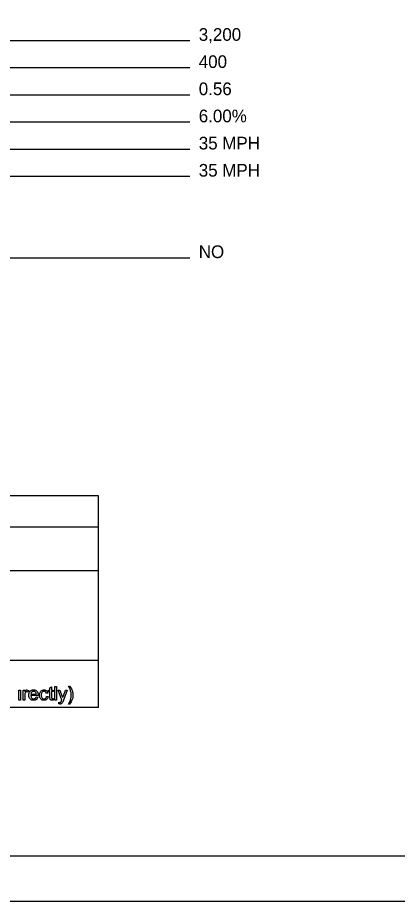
# Model space of a CAD drawing. Extents: x -4 to 116, y -17 to 29.
# Drawn here: x 54.22 to 58.41, y -14.61 to -4.84 of the extents above; entities that cross this region are included whole.
import ezdxf

# ---------------------------------------------------------------- set-up
doc = ezdxf.new("R2010")
doc.units = 0
for name, color, linetype in [('SH_Border', 7, 'Continuous'), ('SH_Cut_Line', 7, 'Continuous'), ('SH_Data', 7, 'Continuous'), ('SH_Text', 7, 'Continuous')]:
    doc.layers.add(name, color=color, linetype=linetype)

msp = doc.modelspace()

# ---------------------------------------------------------------- linework, layer by layer
at = {"layer": 'SH_Border'}
msp.add_lwpolyline([(49.9833, 6.8947), (81.9833, 6.8947), (81.9833, -14.1053), (49.9833, -14.1053)], close=True, dxfattribs=at)
at = {"layer": 'SH_Cut_Line'}
msp.add_lwpolyline([(48.4833, -14.6053), (82.4833, -14.6053), (82.4833, 7.3947), (48.4833, 7.3947)], close=True, dxfattribs=at)
at = {"layer": 'SH_Data'}
for p, q in [((56.1201, -5.0991), (52.6718, -5.0991)), ((56.1201, -5.3991), (53.3556, -5.3991)), ((56.1201, -5.6991), (53.087, -5.6991)), ((56.1201, -5.9991), (52.6718, -5.9991)), ((56.1201, -6.2991), (51.8292, -6.2991)), ((56.1201, -6.5991), (51.7255, -6.5991)), ((56.1201, -7.4991), (51.7502, -7.4991)), ((55.1108, -10.125), (50.8608, -10.125)), ((55.1108, -12.4625), (55.1108, -10.125)), ((50.8608, -10.4666), (55.1108, -10.4666)), ((50.8608, -10.95), (55.1108, -10.95)), ((55.1108, -11.9447), (50.8608, -11.9447)), ((55.1108, -12.4625), (50.8608, -12.4625))]:
    msp.add_line(p, q, dxfattribs=at)
at = {"layer": 'SH_Text'}
for points in [[(54.2342, -12.3814), (54.2342, -12.2726), (54.2526, -12.2726), (54.2526, -12.3814), (54.2342, -12.3814)], [(54.2804, -12.3814), (54.2804, -12.2726), (54.297, -12.2726), (54.297, -12.289)], [(54.3395, -12.276), (54.333, -12.2931)], [(54.5753, -12.3495), (54.5753, -12.2869), (54.5617, -12.2869), (54.5617, -12.2726), (54.5753, -12.2726), (54.5753, -12.2456), (54.5938, -12.2346), (54.5938, -12.2726), (54.6122, -12.2726), (54.6122, -12.2869), (54.5938, -12.2869), (54.5938, -12.3506)], [(54.6298, -12.3814), (54.6298, -12.2312), (54.6482, -12.2312), (54.6482, -12.3814), (54.6298, -12.3814)], [(54.7076, -12.3815), (54.6663, -12.2726), (54.6862, -12.2726), (54.7088, -12.3354)], [(54.7243, -12.336), (54.7476, -12.2726), (54.766, -12.2726), (54.7247, -12.3833)], [(54.7806, -12.2287), (54.7938, -12.2287)], [(54.2988, -12.3244), (54.2988, -12.3814), (54.2804, -12.3814)], [(54.4444, -12.3317), (54.3633, -12.3317)], [(54.3643, -12.3166), (54.4251, -12.3166)], [(54.4249, -12.3463), (54.4439, -12.3487)], [(54.5545, -12.3046), (54.5365, -12.3073)], [(54.5381, -12.3416), (54.5562, -12.344)], [(54.6122, -12.365), (54.6148, -12.3812)], [(54.676, -12.4232), (54.674, -12.4058)], [(54.7938, -12.4256), (54.7806, -12.4256)]]:
    msp.add_lwpolyline(points, dxfattribs=at)
for points in [[(54.297, -12.289), (54.3033, -12.2775), (54.3087, -12.2738), (54.3141, -12.2702), (54.3205, -12.2702), (54.3298, -12.2702), (54.3395, -12.276)], [(54.333, -12.2931), (54.3263, -12.2892), (54.3196, -12.2892), (54.3135, -12.2892), (54.3087, -12.2928), (54.304, -12.2964), (54.3019, -12.3029), (54.2988, -12.3127), (54.2988, -12.3244)], [(54.4439, -12.3487), (54.4394, -12.3654), (54.4272, -12.3746), (54.415, -12.3838), (54.3961, -12.3838), (54.3722, -12.3838), (54.3582, -12.3691), (54.3443, -12.3544), (54.3443, -12.3279), (54.3443, -12.3005), (54.3584, -12.2853), (54.3725, -12.2702), (54.3951, -12.2702), (54.4169, -12.2702), (54.4307, -12.285), (54.4445, -12.2999), (54.4445, -12.3268), (54.4445, -12.3284), (54.4444, -12.3317)], [(54.4251, -12.3166), (54.4238, -12.3028), (54.4181, -12.296), (54.4093, -12.2853), (54.3952, -12.2853), (54.3825, -12.2853), (54.3739, -12.2938), (54.3652, -12.3023), (54.3643, -12.3166)], [(54.5562, -12.344), (54.5532, -12.3627), (54.541, -12.3732), (54.5288, -12.3838), (54.5109, -12.3838), (54.4886, -12.3838), (54.475, -12.3692), (54.4615, -12.3546), (54.4615, -12.3274), (54.4615, -12.3098), (54.4673, -12.2966), (54.4731, -12.2834), (54.4851, -12.2768), (54.497, -12.2702), (54.5111, -12.2702), (54.5288, -12.2702), (54.5401, -12.2791), (54.5513, -12.2881), (54.5545, -12.3046)], [(54.5365, -12.3073), (54.534, -12.2964), (54.5275, -12.2908), (54.521, -12.2853), (54.5118, -12.2853), (54.4979, -12.2853), (54.4892, -12.2953), (54.4805, -12.3052), (54.4805, -12.3269), (54.4805, -12.3488), (54.4889, -12.3587), (54.4973, -12.3687), (54.5108, -12.3687), (54.5216, -12.3687), (54.5289, -12.362), (54.5362, -12.3554), (54.5381, -12.3416)], [(54.7806, -12.4256), (54.8112, -12.3764), (54.8112, -12.3271), (54.8112, -12.3079), (54.8068, -12.2889), (54.8033, -12.2736), (54.7971, -12.2595), (54.7931, -12.2502), (54.7806, -12.2287)], [(54.7938, -12.2287), (54.8131, -12.2544), (54.8223, -12.2803), (54.8302, -12.3027), (54.8302, -12.327), (54.8302, -12.3547), (54.8196, -12.3805), (54.809, -12.4063), (54.7938, -12.4256)], [(54.3633, -12.3317), (54.3643, -12.3496), (54.3734, -12.3592), (54.3825, -12.3687), (54.3962, -12.3687), (54.4063, -12.3687), (54.4135, -12.3633), (54.4207, -12.358), (54.4249, -12.3463)], [(54.6148, -12.3812), (54.607, -12.3829), (54.6009, -12.3829), (54.5909, -12.3829), (54.5854, -12.3797), (54.5798, -12.3765), (54.5776, -12.3713), (54.5753, -12.3662), (54.5753, -12.3495)], [(54.5938, -12.3506), (54.5938, -12.3585), (54.5947, -12.3608), (54.5957, -12.363), (54.5979, -12.3644), (54.6001, -12.3657), (54.6041, -12.3657), (54.6072, -12.3657), (54.6122, -12.365)], [(54.674, -12.4058), (54.68, -12.4075), (54.6845, -12.4075), (54.6907, -12.4075), (54.6943, -12.4054), (54.698, -12.4034), (54.7004, -12.3997), (54.7021, -12.3969), (54.706, -12.386), (54.7065, -12.3845), (54.7076, -12.3815)], [(54.7247, -12.3833), (54.7181, -12.4012), (54.7144, -12.4079), (54.7094, -12.417), (54.7031, -12.4212), (54.6967, -12.4255), (54.6879, -12.4255), (54.6826, -12.4255), (54.676, -12.4232)], [(54.7088, -12.3354), (54.7132, -12.3473), (54.7167, -12.3605), (54.7199, -12.3481), (54.7243, -12.336)]]:
    msp.add_open_spline(points, degree=3, dxfattribs=at)

# ---------------------------------------------------------------- texts
for s, p in [('3,200', (56.2201, -5.0991)), ('400', (56.2201, -5.3991)), ('0.56', (56.2201, -5.6991)), ('6.00%', (56.2201, -5.9991)), ('35 MPH', (56.2201, -6.2991)), ('35 MPH', (56.2201, -6.5991)), ('NO', (56.2201, -7.4991))]:
    msp.add_text(s, height=0.14, dxfattribs=at).set_placement(p)

doc.saveas('drawing.dxf')
